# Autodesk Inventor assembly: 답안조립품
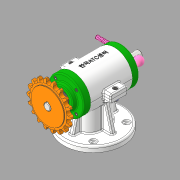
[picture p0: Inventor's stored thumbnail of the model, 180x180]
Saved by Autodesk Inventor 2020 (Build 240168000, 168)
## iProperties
Created: 2021-12
Part Number: 답안조립품
Document SubType Name: Assembly
Designer: MIRAE
Mass: 1663.22 g
Surface Area: 1369.29 cm^2
Volume: 434.957 cm^3
Density: 3.82388 g/cm^3
Author: MIRAE
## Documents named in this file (19)
- C:\Users\MIRAE\Desktop\611206V1028\답안조립품.iam
- C:\Users\MIRAE\Desktop\611206V1028\본체.ipt
- C:\Users\MIRAE\Desktop\611206V1028\상부커버.ipt
- C:\Users\MIRAE\Desktop\611206V1028\앞커버.ipt
- C:\Users\MIRAE\Desktop\611206V1028\뒤커버.ipt
- C:\Users\MIRAE\Desktop\611206V1028\베어링 6201.ipt
- C:\Users\MIRAE\Desktop\611206V1028\베어링 6202.ipt
- C:\Users\MIRAE\Desktop\611206V1028\오일실 12 x 22 x 7.ipt
- C:\Users\MIRAE\Desktop\611206V1028\편심축.ipt
- C:\Users\MIRAE\Desktop\611206V1028\볼트 M3 x 0.5.ipt
- C:\Users\MIRAE\Desktop\611206V1028\키 4 x 4.ipt
- C:\Users\MIRAE\Desktop\611206V1028\스프로킷.ipt
- C:\Users\MIRAE\Desktop\611206V1028\멈춤나사 M3.ipt
- C:\Users\MIRAE\Desktop\611206V1028\가변스프링.ipt
- C:\Users\MIRAE\Desktop\611206V1028\슬라이드.ipt
- C:\Users\MIRAE\Desktop\611206V1028\너트 M4.ipt
- C:\Users\MIRAE\Desktop\611206V1028\와셔.ipt
- C:\Users\MIRAE\Desktop\611206V1028\볼트 M4 x 16.ipt
- C:\Users\MIRAE\Desktop\611206V1028\레버.ipt
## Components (7 placed, 4 different names)
1. 가변스프링:1 — 각도:4
2. ISO 4032 M4:1 — 각도:7
3. ISO 7091 ST 4 - 100 HV:1
4. ISO 4762 M4 x 16:1 — 각도:5
5. ISO 4032 M4:2 — 각도:8
6. ISO 7091 ST 4 - 100 HV:2
7. ISO 4762 M4 x 16:2 — 각도:6
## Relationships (5: Angle 5)
- 각도:4 [Angle]: 가변스프링:1
- 각도:5 [Angle]: ISO 4762 M4 x 16:1
- 각도:6 [Angle]: ISO 4762 M4 x 16:2
- 각도:7 [Angle]: ISO 4032 M4:1
- 각도:8 [Angle]: ISO 4032 M4:2
## Named parameters: d45_d44 = 0
